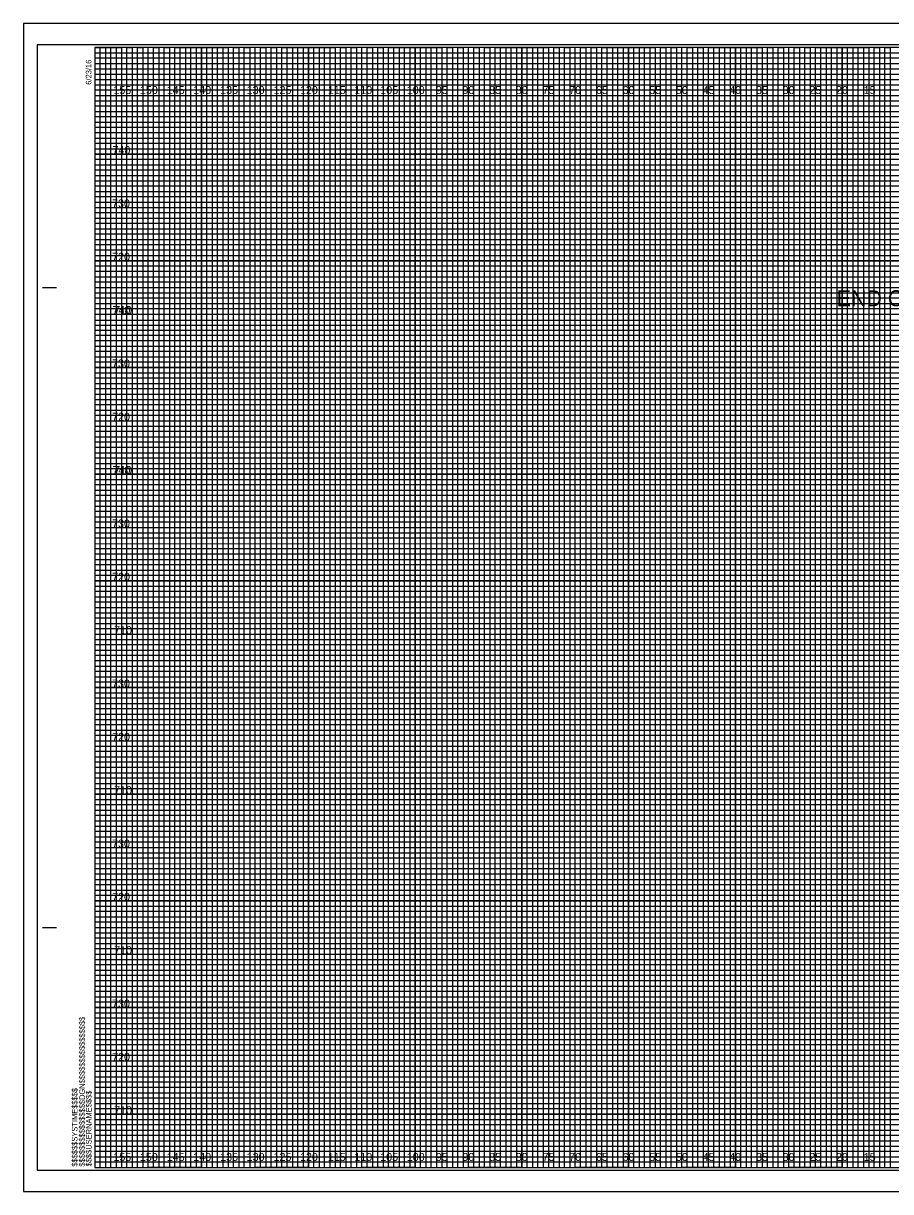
# Model space of a CAD drawing. Extents: x -13 to 323, y -5 to 654.
# Drawn here: x -13.4 to 149.1, y 215.5 to 434.5 of the extents above; entities that cross this region are included whole.
import ezdxf

# ---------------------------------------------------------------- set-up
doc = ezdxf.new("R2010")
doc.units = 0
for name, color, linetype in [('Exist Cross Section Cell', 7, 'Continuous'), ('Exist XS Center Line Elevation Label', 7, 'Continuous'), ('Exist XS Ground Line', 7, 'Continuous'), ('Prop CMT Pvmt Course 1', 7, 'Continuous'), ('Prop CMT Pvmt Course 2', 7, 'Continuous'), ('Prop CMT Pvmt Course 3', 7, 'Continuous'), ('Prop CMT Pvmt Surface', 7, 'Continuous'), ('Prop CMT Pvmt Surface Shoulder', 7, 'Continuous'), ('Prop CMT Shld Paved Course 1', 7, 'Continuous'), ('Prop CMT Shld Paved Course 2', 7, 'Continuous'), ('Prop CMT Subgrade Earthwork', 7, 'Continuous'), ('Scratch_Level_1', 7, 'Continuous')]:
    doc.layers.add(name, color=color, linetype=linetype)

msp = doc.modelspace()

# ---------------------------------------------------------------- linework, layer by layer
at = {"layer": 'Exist XS Center Line Elevation Label'}
for points in [[(0, 430), (5, 430), (5, 220), (15, 220), (15, 430), (25, 430), (25, 220), (35, 220), (35, 430), (45, 430), (45, 220), (55, 220), (55, 430), (65, 430), (65, 220), (75, 220), (75, 430), (85, 430), (85, 220), (95, 220), (95, 430), (105, 430), (105, 220), (115, 220), (115, 430), (125, 430), (125, 220), (135, 220), (135, 430), (145, 430), (145, 220), (155, 220)], [(0, 425), (275, 425)], [(0, 405), (320, 405), (320, 415), (0, 415)], [(0, 385), (320, 385), (320, 395), (0, 395)], [(0, 365), (320, 365), (320, 375), (0, 375)], [(0, 345), (320, 345), (320, 355), (0, 355)], [(0, 325), (320, 325), (320, 335), (0, 335)], [(0, 305), (320, 305), (320, 315), (0, 315)], [(0, 285), (320, 285), (320, 295), (0, 295)], [(0, 265), (320, 265), (320, 275), (0, 275)], [(0, 245), (320, 245), (320, 255), (0, 255)], [(0, 225), (320, 225), (320, 235), (0, 235)]]:
    msp.add_lwpolyline(points, dxfattribs=at)
at = {"layer": 'Exist XS Ground Line'}
for p, q in [((10, 430), (0, 430)), ((10, 220), (10, 430)), ((30, 430), (20, 430)), ((20, 430), (20, 220)), ((30, 220), (30, 430)), ((50, 430), (40, 430)), ((40, 430), (40, 220)), ((50, 220), (50, 430)), ((70, 430), (60, 430)), ((60, 430), (60, 220)), ((70, 220), (70, 430)), ((90, 430), (80, 430)), ((80, 430), (80, 220)), ((90, 220), (90, 430)), ((110, 430), (100, 430)), ((100, 430), (100, 220)), ((110, 220), (110, 430)), ((130, 430), (120, 430)), ((120, 430), (120, 220)), ((130, 220), (130, 430)), ((150, 430), (140, 430)), ((140, 430), (140, 220)), ((20, 220), (10, 220)), ((40, 220), (30, 220)), ((60, 220), (50, 220)), ((80, 220), (70, 220)), ((100, 220), (90, 220)), ((120, 220), (110, 220)), ((140, 220), (130, 220))]:
    msp.add_line(p, q, dxfattribs=at)
for points in [[(0, 420), (320, 420), (320, 410), (0, 410)], [(0, 400), (320, 400), (320, 390), (0, 390)], [(0, 380), (320, 380), (320, 370), (0, 370)], [(0, 360), (320, 360), (320, 350), (0, 350)], [(0, 340), (320, 340), (320, 330), (0, 330)], [(0, 320), (320, 320), (320, 310), (0, 310)], [(0, 300), (320, 300), (320, 290), (0, 290)], [(0, 280), (320, 280), (320, 270), (0, 270)], [(0, 260), (320, 260), (320, 250), (0, 250)], [(0, 240), (320, 240), (320, 230), (0, 230)]]:
    msp.add_lwpolyline(points, dxfattribs=at)
at = {"layer": 'Prop CMT Pvmt Course 2'}
msp.add_lwpolyline([(-13.4, 215.5), (323.3, 215.5), (323.3, 434.5), (-13.4, 434.5)], close=True, dxfattribs=at)
at = {"layer": 'Prop CMT Pvmt Course 3'}
msp.add_lwpolyline([(-10.8, 219.5), (322.4, 219.5), (322.4, 430.5), (-10.8, 430.5)], close=True, dxfattribs=at)
msp.add_lwpolyline([(-10.8, 219.5), (322.4, 219.5), (322.4, 430.5), (-10.8, 430.5)], close=True, dxfattribs=at)
at = {"layer": 'Prop CMT Pvmt Surface'}
for p, q in [((323.3, 434.5), (-13.4, 434.5)), ((-13.4, 434.5), (-13.4, 215.5)), ((323.3, 434.5), (-13.4, 434.5)), ((-13.4, 434.5), (-13.4, 215.5)), ((-13.4, 215.5), (323.3, 215.5)), ((-13.4, 215.5), (323.3, 215.5))]:
    msp.add_line(p, q, dxfattribs=at)
at = {"layer": 'Prop CMT Shld Paved Course 1'}
for p, q in [((-9.8, 385), (-7.3, 385)), ((-9.7, 385), (-7.2, 385)), ((-9.8, 265), (-7.3, 265)), ((-9.7, 265), (-7.2, 265)), ((0, 220), (0, 220)), ((0, 220), (0, 220)), ((0, 220), (0, 220)), ((0, 220), (0, 220)), ((0, 220), (0, 220)), ((0, 220), (0, 220)), ((0, 220), (0, 220))]:
    msp.add_line(p, q, dxfattribs=at)
msp.add_lwpolyline([(320, 430), (0, 430), (0, 220), (320, 220)], close=True, dxfattribs=at)
at = {"layer": 'Prop CMT Shld Paved Course 2'}
for points in [[(0, 220), (1, 220), (1, 430), (2, 430), (2, 220)], [(2, 220), (3, 220), (3, 430), (4, 430), (4, 220)], [(5, 220), (6, 220), (6, 430), (7, 430), (7, 220)], [(7, 220), (8, 220), (8, 430), (9, 430), (9, 220)], [(10, 220), (11, 220), (11, 430), (12, 430), (12, 220)], [(12, 220), (13, 220), (13, 430), (14, 430), (14, 220)], [(15, 220), (16, 220), (16, 430), (17, 430), (17, 220)], [(17, 220), (18, 220), (18, 430), (19, 430), (19, 220)], [(20, 220), (21, 220), (21, 430), (22, 430), (22, 220)], [(22, 220), (23, 220), (23, 430), (24, 430), (24, 220)], [(25, 220), (26, 220), (26, 430), (27, 430), (27, 220)], [(27, 220), (28, 220), (28, 430), (29, 430), (29, 220)], [(30, 220), (31, 220), (31, 430), (32, 430), (32, 220)], [(32, 220), (33, 220), (33, 430), (34, 430), (34, 220)], [(35, 220), (36, 220), (36, 430), (37, 430), (37, 220)], [(37, 220), (38, 220), (38, 430), (39, 430), (39, 220)], [(40, 220), (41, 220), (41, 430), (42, 430), (42, 220)], [(42, 220), (43, 220), (43, 430), (44, 430), (44, 220)], [(45, 220), (46, 220), (46, 430), (47, 430), (47, 220)], [(47, 220), (48, 220), (48, 430), (49, 430), (49, 220)], [(50, 220), (51, 220), (51, 430), (52, 430), (52, 220)], [(52, 220), (53, 220), (53, 430), (54, 430), (54, 220)], [(55, 220), (56, 220), (56, 430), (57, 430), (57, 220)], [(57, 220), (58, 220), (58, 430), (59, 430), (59, 220)], [(60, 220), (61, 220), (61, 430), (62, 430), (62, 220)], [(62, 220), (63, 220), (63, 430), (64, 430), (64, 220)], [(65, 220), (66, 220), (66, 430), (67, 430), (67, 220)], [(67, 220), (68, 220), (68, 430), (69, 430), (69, 220)], [(70, 220), (71, 220), (71, 430), (72, 430), (72, 220)], [(72, 220), (73, 220), (73, 430), (74, 430), (74, 220)], [(75, 220), (76, 220), (76, 430), (77, 430), (77, 220)], [(77, 220), (78, 220), (78, 430), (79, 430), (79, 220)], [(80, 220), (81, 220), (81, 430), (82, 430), (82, 220)], [(82, 220), (83, 220), (83, 430), (84, 430), (84, 220)], [(85, 220), (86, 220), (86, 430), (87, 430), (87, 220)], [(87, 220), (88, 220), (88, 430), (89, 430), (89, 220)], [(90, 220), (91, 220), (91, 430), (92, 430), (92, 220)], [(92, 220), (93, 220), (93, 430), (94, 430), (94, 220)], [(95, 220), (96, 220), (96, 430), (97, 430), (97, 220)], [(97, 220), (98, 220), (98, 430), (99, 430), (99, 220)], [(100, 220), (101, 220), (101, 430), (102, 430), (102, 220)], [(102, 220), (103, 220), (103, 430), (104, 430), (104, 220)], [(105, 220), (106, 220), (106, 430), (107, 430), (107, 220)], [(107, 220), (108, 220), (108, 430), (109, 430), (109, 220)], [(110, 220), (111, 220), (111, 430), (112, 430), (112, 220)], [(112, 220), (113, 220), (113, 430), (114, 430), (114, 220)], [(115, 220), (116, 220), (116, 430), (117, 430), (117, 220)], [(117, 220), (118, 220), (118, 430), (119, 430), (119, 220)], [(120, 220), (121, 220), (121, 430), (122, 430), (122, 220)], [(122, 220), (123, 220), (123, 430), (124, 430), (124, 220)], [(125, 220), (126, 220), (126, 430), (127, 430), (127, 220)], [(127, 220), (128, 220), (128, 430), (129, 430), (129, 220)], [(130, 220), (131, 220), (131, 430), (132, 430), (132, 220)], [(132, 220), (133, 220), (133, 430), (134, 430), (134, 220)], [(135, 220), (136, 220), (136, 430), (137, 430), (137, 220)], [(137, 220), (138, 220), (138, 430), (139, 430), (139, 220)], [(140, 220), (141, 220), (141, 430), (142, 430), (142, 220)], [(142, 220), (143, 220), (143, 430), (144, 430), (144, 220)], [(145, 220), (146, 220), (146, 430), (147, 430), (147, 220)], [(147, 220), (148, 220), (148, 430), (149, 430), (149, 220)]]:
    msp.add_lwpolyline(points, dxfattribs=at)
at = {"layer": 'Prop CMT Subgrade Earthwork'}
for p, q in [((10, 220), (10, 430)), ((10, 220), (10, 430)), ((20, 220), (20, 430)), ((20, 220), (20, 430)), ((30, 220), (30, 430)), ((30, 220), (30, 430)), ((40, 220), (40, 430)), ((40, 220), (40, 430)), ((50, 220), (50, 430)), ((50, 220), (50, 430)), ((60, 220), (60, 430)), ((60, 220), (60, 430)), ((70, 220), (70, 430)), ((70, 220), (70, 430)), ((80, 220), (80, 430)), ((80, 220), (80, 430)), ((90, 220), (90, 430)), ((90, 220), (90, 430)), ((100, 220), (100, 430)), ((100, 220), (100, 430)), ((110, 220), (110, 430)), ((110, 220), (110, 430)), ((120, 220), (120, 430)), ((120, 220), (120, 430)), ((130, 220), (130, 430)), ((130, 220), (130, 430)), ((140, 220), (140, 430)), ((140, 220), (140, 430)), ((0, 420), (320, 420)), ((0, 420), (320, 420)), ((0, 410), (320, 410)), ((0, 410), (320, 410)), ((0, 400), (320, 400)), ((0, 400), (320, 400)), ((0, 390), (320, 390)), ((0, 390), (320, 390)), ((0, 380), (320, 380)), ((0, 380), (320, 380)), ((0, 370), (320, 370)), ((0, 370), (320, 370)), ((0, 360), (320, 360)), ((0, 360), (320, 360)), ((0, 350), (320, 350)), ((0, 350), (320, 350)), ((0, 340), (320, 340)), ((0, 340), (320, 340)), ((0, 330), (320, 330)), ((0, 330), (320, 330)), ((0, 320), (320, 320)), ((0, 320), (320, 320)), ((0, 310), (320, 310)), ((0, 310), (320, 310)), ((0, 300), (320, 300)), ((0, 300), (320, 300)), ((0, 290), (320, 290)), ((0, 290), (320, 290)), ((0, 280), (320, 280)), ((0, 280), (320, 280)), ((0, 270), (320, 270)), ((0, 270), (320, 270)), ((0, 260), (320, 260)), ((0, 260), (320, 260)), ((0, 250), (320, 250)), ((0, 250), (320, 250)), ((0, 240), (320, 240)), ((0, 240), (320, 240)), ((0, 230), (320, 230)), ((0, 230), (320, 230))]:
    msp.add_line(p, q, dxfattribs=at)
at = {"layer": 'Scratch_Level_1'}
for p, q in [((0, 429), (260, 429)), ((260, 427.98), (0, 427.98)), ((0, 427.98), (0, 427)), ((0, 427), (260, 427)), ((260, 425.89), (0, 425.89)), ((0, 425.89), (0, 424)), ((0, 424), (320, 424))]:
    msp.add_line(p, q, dxfattribs=at)
for points in [[(0, 423), (270, 423), (320, 423), (320, 422), (0, 422)], [(0, 421), (320, 421), (320, 419), (0, 419)], [(0, 418), (320, 418), (320, 417), (0, 416.98)], [(0, 416), (320, 416), (320, 414), (0, 414)], [(0, 413), (320, 413), (320, 412), (0, 412)], [(0, 411), (320, 411), (320, 409), (0, 409)], [(0, 408), (320, 408), (320, 407), (0, 407)], [(0, 406), (320, 406), (320, 404), (0, 404)], [(0, 403), (320, 403), (320, 402), (0, 402)], [(0, 401), (320, 401), (320, 399), (0, 399)], [(0, 398), (320, 398), (320, 397), (0, 397)], [(0, 396), (320, 396), (320, 393.95), (320, 393), (320, 392), (0, 392)], [(0, 394), (320, 394), (320, 393), (0, 393)], [(0, 391), (320, 391), (320, 389), (0, 389.03)], [(0, 389.03), (320, 389), (320, 388), (0, 388)], [(0, 387), (320, 387), (320, 386), (0, 386)], [(0, 384), (320, 384), (320, 383), (0, 383)], [(0, 382), (320, 382), (320, 381), (0, 381)], [(-0.07, 378.89), (320, 378.89), (320, 377.88), (-0.07, 377.88)], [(0, 377), (320, 377), (320, 376), (0, 376)], [(0, 374), (320, 374), (320, 373), (0, 373)], [(0, 372), (320, 372), (320, 371), (0, 371)], [(0, 369), (320, 369), (320, 368), (0, 368)], [(0, 367), (320, 367), (320, 366), (0, 366)], [(0, 364), (320, 364), (320, 363), (0, 363)], [(0, 362), (320, 362), (320, 361), (0, 361)], [(0, 359), (320, 359), (319.99, 357.98), (0, 358)], [(0, 357), (320, 357), (320, 356), (0, 356)], [(0, 354), (320, 354), (320, 353), (0, 353)], [(0, 352), (320, 352), (320, 351), (0, 351)], [(0, 349), (320, 349), (320, 348), (0, 348)], [(0, 347), (320, 347), (320, 346), (0, 346)], [(0, 344), (320, 344), (320, 343), (0, 343)], [(0, 342), (320, 342), (320, 341), (0, 341)], [(0, 339), (320, 339), (320, 338), (0, 338)], [(0, 336.99), (320.07, 336.91), (320, 336), (0, 336)], [(0, 334), (320, 334), (320, 333), (0, 333)], [(0, 332), (320, 332), (320, 331), (0, 331)], [(0, 329), (320, 329), (320, 328), (0, 328)], [(0, 327), (320, 327), (320, 326), (0, 326)], [(0, 324), (320, 324), (320, 323), (0, 323)], [(0, 322), (320, 322), (320, 321), (0, 321)], [(0, 319), (320, 319), (320, 318), (0, 318)], [(0, 317), (320, 317), (320, 316), (0, 316)], [(0, 314), (320, 314), (320, 313), (0, 313)], [(0, 312), (320, 312), (320, 311), (0, 311)], [(0, 309), (320, 309), (320, 308), (0, 308)], [(0, 307), (320, 307), (320, 306), (0, 306)], [(0, 304), (320, 304), (320, 303), (0, 303)], [(0, 302), (320, 302), (320, 301), (0, 301)], [(0, 299), (320, 299), (319.99, 297.98), (0, 298)], [(0, 297), (320, 297), (320, 296), (0, 296)], [(0, 294), (320, 294), (320, 293), (0, 293)], [(0, 292), (320, 292), (320, 291), (0, 291)], [(0, 289), (320, 289), (320, 288), (0, 288)], [(0, 287), (320, 287), (320, 286), (0, 286)], [(0, 284), (320, 284), (320, 283), (0, 283)], [(0, 282), (320, 282), (320, 281), (0, 281)], [(0, 279), (320, 279), (320, 278), (0, 278)], [(0, 276.99), (320.07, 276.91), (320, 276), (0, 276)], [(0, 274), (320, 274), (320, 273), (0, 273)], [(0, 272), (320, 272), (320, 271), (0, 271)], [(0, 269), (320, 269), (320, 268), (0, 268)], [(0, 267), (320, 267), (320, 266), (0, 266)], [(0, 264), (320, 264), (320, 263), (0, 263)], [(0, 262), (320, 262), (320, 261), (0, 261)], [(0, 259), (320, 259), (320, 258), (0, 258)], [(0, 257), (320, 257), (320, 256), (0, 256)], [(0, 254), (320, 254), (320, 253), (0, 253)], [(0, 252), (320, 252), (320, 251), (0, 251)], [(0, 249), (320, 249), (320, 248), (0, 248)], [(0, 247), (320, 247), (320, 246), (0, 246)], [(0, 244), (320, 244), (320, 243), (0, 243)], [(0, 242), (320, 242), (320, 241), (0, 241)], [(0, 239), (320, 239), (320, 238), (0, 238)], [(0, 237), (320, 237), (320, 236), (0, 236)], [(0, 234), (320, 234), (320, 233), (0, 233)], [(0, 232), (320, 232), (320, 231), (0, 231)], [(0, 229), (320, 229), (320, 228), (0, 228)], [(0, 227), (320, 227), (320, 226), (0, 226)], [(0, 224), (320, 224), (320, 223), (0, 223)], [(0, 222), (320, 222), (320, 221), (0, 221)]]:
    msp.add_lwpolyline(points, dxfattribs=at)

# ---------------------------------------------------------------- texts
at = {"layer": 'Exist Cross Section Cell'}
for s, p in [('155', (3.47, 421.25)), ('150', (8.44, 421.25)), ('145', (13.47, 421.25)), ('140', (18.44, 421.25)), ('135', (23.47, 421.25)), ('130', (28.44, 421.25)), ('125', (33.47, 421.25)), ('120', (38.44, 421.25)), ('115', (43.65, 421.25)), ('110', (48.62, 421.25)), ('105', (53.47, 421.25)), ('100', (58.44, 421.25)), ('95', (63.88, 421.25)), ('90', (68.86, 421.25)), ('85', (73.88, 421.25)), ('80', (78.86, 421.25)), ('75', (83.88, 421.25)), ('70', (88.86, 421.25)), ('65', (93.88, 421.25)), ('60', (98.86, 421.25)), ('55', (103.88, 421.25)), ('50', (108.86, 421.25)), ('45', (113.88, 421.25)), ('40', (118.86, 421.25)), ('35', (123.88, 421.25)), ('30', (128.86, 421.25)), ('25', (133.88, 421.25)), ('20', (138.86, 421.25)), ('15', (144.06, 421.25)), ('155', (3.47, 221.25)), ('150', (8.44, 221.25)), ('145', (13.47, 221.25)), ('140', (18.44, 221.25)), ('135', (23.47, 221.25)), ('130', (28.44, 221.25)), ('125', (33.47, 221.25)), ('120', (38.44, 221.25)), ('115', (43.65, 221.25)), ('110', (48.62, 221.25)), ('105', (53.47, 221.25)), ('100', (58.44, 221.25)), ('95', (63.88, 221.25)), ('90', (68.86, 221.25)), ('85', (73.88, 221.25)), ('80', (78.86, 221.25)), ('75', (83.88, 221.25)), ('70', (88.86, 221.25)), ('65', (93.88, 221.25)), ('60', (98.86, 221.25)), ('55', (103.88, 221.25)), ('50', (108.86, 221.25)), ('45', (113.88, 221.25)), ('40', (118.86, 221.25)), ('35', (123.88, 221.25)), ('30', (128.86, 221.25)), ('25', (133.88, 221.25)), ('20', (138.86, 221.25)), ('15', (144.06, 221.25))]:
    msp.add_text(s, height=1.5, dxfattribs=at).set_placement(p)
at = {"layer": 'Prop CMT Pvmt Course 1'}
msp.add_text('END CONSTRUCTION', height=3, dxfattribs=at).set_placement((138.99, 381.47))
at = {"layer": 'Prop CMT Pvmt Surface Shoulder'}
for s, p in [('740', (3.3, 410)), ('730', (3.22, 400)), ('720', (3.23, 390)), ('740', (3.3, 380)), ('710', (3.61, 380)), ('730', (3.22, 370)), ('720', (3.23, 360)), ('740', (3.3, 350)), ('710', (3.61, 350)), ('730', (3.22, 340)), ('720', (3.23, 330)), ('710', (3.61, 320)), ('730', (3.22, 310)), ('720', (3.23, 300)), ('710', (3.61, 290)), ('730', (3.22, 280)), ('720', (3.23, 270)), ('710', (3.61, 260)), ('730', (3.22, 250)), ('720', (3.23, 240)), ('710', (3.61, 230))]:
    msp.add_text(s, height=1.5, dxfattribs=at).set_placement(p)
at = {"layer": 'Prop CMT Shld Paved Course 1'}
for s, p in [('6/23/16', (-0.65, 423)), ('$$$$$$$$$$$$$$$$DGN$$$$$$$$$$$$$$$$', (-1.88, 220.18)), ('$$$$$$SYSTIME$$$$$', (-3.26, 220.18)), ('$$$$USERNAME$$$$', (-0.62, 220.23))]:
    msp.add_text(s, height=1.05, rotation=90, dxfattribs=at).set_placement(p)

doc.saveas('drawing.dxf')
